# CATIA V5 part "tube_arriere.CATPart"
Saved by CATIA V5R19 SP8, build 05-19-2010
Part number: tube_arriere
Bounding box of the stored display mesh (mm): x -420 to 420, y -20 to 1000, z -20 to 68
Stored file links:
  U:\Thinkmotion\Assemblage final\tube_arriere.CATPart
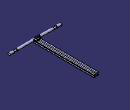
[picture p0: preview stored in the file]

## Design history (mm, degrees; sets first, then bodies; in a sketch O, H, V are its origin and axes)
Body1 (main body)
  Sketch1 on yz-plane, origin (0, 0, 0), H (0, 1, 0), V (0, 0, 1)
    circle A1 centre (0, 0) radius 20
    radius A1 = 20
  Pad1: profile Sketch1, direction (1, 0, 0), length 300
  Mirror1: of Pad1, Sketch1, about yz-plane
  Sketch2 on zx-plane, origin (0, 0, 0), H (-1, 0, 0), V (0, 0, 1)
    reference projected line E1 through (0, 0) direction (-1, 0) from axis of face of Mirror1
    reference intersected line E2 through (0, 0) direction (0, -1) from yz-plane
    point P5 (0, 18)
    line L1 (0, 18) -> (-40, 18)
    point P6 (-40, 18)
    line L2 (-40, 18) -> (-40, 15)
    point P7 (-40, 15)
    line L3 (-40, 15) -> (-20, 15)
    point P8 (-20, 15)
    line L4 (-20, 15) -> (-20, 0)
    point P9 (-20, 0)
    point P10 (0, -18)
    point P11 (-40, -18)
    point P12 (-40, -15)
    point P13 (-20, -15)
    point P14 (-20, 0)
    line L5 (0, -18) -> (-40, -18)
    line L6 (-40, -18) -> (-40, -15)
    line L7 (-20, -15) -> (-20, 0)
    line L8 (-40, -15) -> (-20, -15)
    point P15 (0, 18)
    point P16 (40, 18)
    point P17 (40, 15)
    point P18 (20, 15)
    point P19 (20, 0)
    point P20 (0, -18)
    point P21 (40, -18)
    point P22 (40, -15)
    point P23 (20, -15)
    point P24 (20, 0)
    line L9 (0, 18) -> (40, 18)
    line L10 (40, 18) -> (40, 15)
    line L11 (40, 15) -> (20, 15)
    line L12 (20, 15) -> (20, 0)
    line L13 (0, -18) -> (40, -18)
    line L14 (40, -18) -> (40, -15)
    line L15 (20, -15) -> (20, 0)
    line L16 (40, -15) -> (20, -15)
    length L2 = 3
    length L1 = 40
    distance P9 O = 20
    distance O P5 = 18
    horizontal: L1 H, L3 H
    vertical: L2 V, L4 V
    symmetry: P5 P10 E1, P6 P11 E1, P7 P12 E1, P8 P13 E1, P9 P14 E1, L1 L5 E1, L2 L6 E1, L4 L7 E1, L3 L8 E1, P5 P15 E2, P6 P16 E2, P7 P17 E2, P8 P18 E2, P9 P19 E2, P10 P20 E2, P11 P21 E2, P12 P22 E2, P13 P23 E2, P14 P24 E2, L1 L9 E2, L2 L10 E2, L3 L11 E2, L4 L12 E2, L5 L13 E2, L6 L14 E2, L7 L15 E2, L8 L16 E2
  Pad2: profile Sketch2, direction (0, 1, 0), length 1000
  Sketch3 on end face of Pad1, origin (300, 0, 0), H (0, 1, 0), V (0, 0, 1)
    circle A1 centre (0, 0) radius 10
    reference projected circle E1 centre (0, 0) radius 20 from edge [face of Mirror1 | end face of Pad1]
    radius A1 = 10
    concentricity: A1 E1
  Pad3: profile Sketch3, direction (1, 0, 0), length 50
  Mirror2: of Pad3, Sketch3, about yz-plane
  Sketch4 on end face of Pad3, origin (350, 0, 0), H (0, 1, 0), V (0, 0, 1)
    circle A1 centre (0, 0) radius 20
    reference projected circle E1 centre (0, 0) radius 20 from edge [face of Mirror1 | end face of Pad1]
    coincidence: E1 A1
  Pad4: profile Sketch4, direction (1, 0, 0), length 70
  Mirror3: of Pad4, Sketch4, about yz-plane
  Sketch5 on end face of Pad2, origin (0, 1000, 0), H (-1, 0, 0), V (0, 0, 1)
    point P1 (-1.5, 30)
    line L1 (-1.5, 30) -> (0, 30)
    line L2 (0, -40) -> (-1.5, -40)
    line L3 (-1.5, -40) -> (-1.5, 30)
    point P2 (0, 30)
    point P3 (0, -40)
    point P4 (-1.5, -40)
    point P5 (1.5, 30)
    point P6 (0, 30)
    point P7 (0, -40)
    point P8 (1.5, -40)
    line L4 (1.5, 30) -> (0, 30)
    line L5 (0, -40) -> (1.5, -40)
    line L6 (1.5, -40) -> (1.5, 30)
    length L1 = 1.5
    horizontal: L1 H, L2 H
    vertical: L3 V
    symmetry: P1 P5 V, P2 P6 V, P3 P7 V, P4 P8 V, L1 L4 V, L2 L5 V, L3 L6 V
    coincidence: P2 P6, P3 P7
  Pocket1: profile Sketch5, direction (0, -1, 0), length 100
  Sketch6 on face of Pad2 from Sketch2.L7, origin (20, 983.6912, -1.7142), H (0, 1, 0), V (0, 0, 1)
    point P1 (1.3088, 1.7142)
    reference projected line E1 (-983.6912, 1.7142) -> (16.3088, 1.7142) from edge [face of Pad2 from Sketch2.L7 | face of Pad2 from Sketch2.L4]
    reference projected line E2 (16.3088, 16.7142) -> (16.3088, 1.7142) from edge [face of Pad2 from Sketch2.L4 | end face of Pad2]
    distance P1 E2 = 15
    coincidence: P1 E1
  Hole1: placed by Sketch6, at (20, 985, 0) direction (-1, 0, 0), diameter 10, through (limit type 3)
  Sketch7 on yz-plane, origin (0, 0, 0), H (0, 1, 0), V (0, 0, 1)
    point P1 (20, -18)
    point P2 (60, -18)
    point P3 (60, -48)
    point P4 (20, 18)
    point P5 (60, 18)
    point P8 (60, 48)
    line L1 (20, 18) -> (60, 18)
    line L2 (60, 18) -> (60, 48)
    line L3 (20, 48) -> (20, 18)
    arc A1 centre (40, 48) radius 20 from (20, 48) to (60, 48) cw
    distance P1 P2 = 40
    distance P2 P3 = 30
    symmetry: P1 P4 H, P2 P5 H, P3 P8 H
  Pad5: profile Sketch7, direction (1, 0, 0), length 30, mirrored extent
  Sketch8 on zx-plane, origin (0, 0, 0), H (-1, 0, 0), V (0, 0, 1)
    line L1 (-20, 30) -> (20, 30)
    line L2 (20, 30) -> (20, 90)
    line L3 (20, 90) -> (-20, 90)
    line L4 (-20, 90) -> (-20, 30)
    construction line L5 (30, 68) -> (30, 48)
    construction line L6 (-30, 68) -> (-30, 48)
  Pocket2: profile Sketch8, direction (0, 1, 0), length 75
  Sketch9 on end face of Pad5, origin (30, 51.1286, 37.6058), H (0, 1, 0), V (0, 0, 1)
    point P1 (-11.1286, 10.3942)
    reference projected arc E1 centre (-11.1286, 10.3942) radius 20 from (8.8714, 10.3942) to (-31.1286, 10.3942) ccw from edge [face of Pad5 from Sketch7.A1 | end face of Pad5]
    concentricity: P1 E1
  Hole2: placed by Sketch9, at (30, 40, 48) direction (-1, 0, 0), diameter 10, through (limit type 3)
